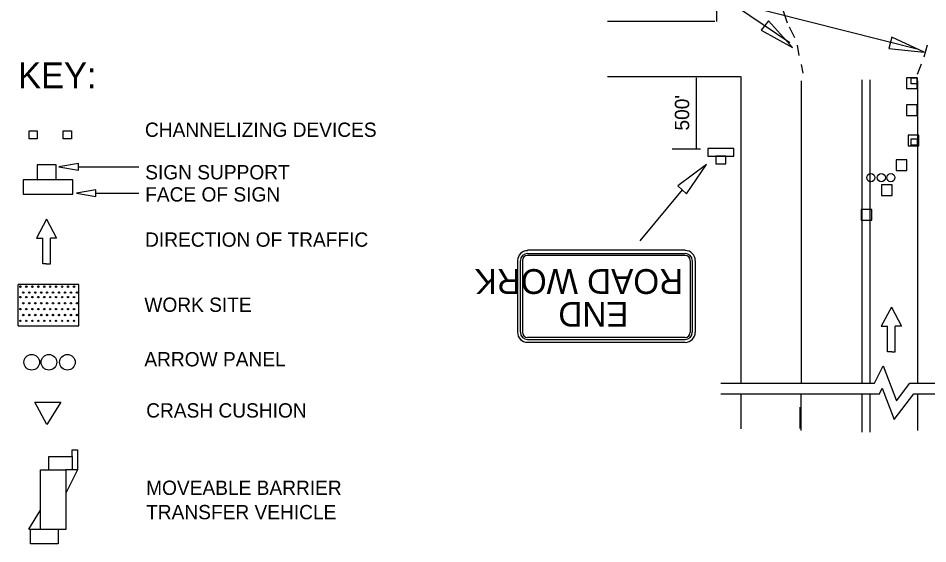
# Model space of a CAD drawing. Extents: x 1531.4 to 1538.6, y 1529.6 to 1539.6.
# Drawn here: x 1532.047 to 1535.863, y 1531.428 to 1533.633 of the extents above; entities that cross this region are included whole.
import ezdxf

# ---------------------------------------------------------------- set-up
doc = ezdxf.new("R2010")
doc.units = 0
for name, color, linetype in [('DETL-DIMS', 7, 'Continuous'), ('DETL-LINE', 7, 'Continuous'), ('DETL-NOTE', 7, 'Continuous'), ('DETL-TITL', 7, 'Continuous'), ('USER-BORD', 7, 'Continuous')]:
    doc.layers.add(name, color=color, linetype=linetype)

# ---------------------------------------------------------------- blocks, each defined once
blk = doc.blocks.new('CD1')
at = {"layer": 'USER-BORD'}
blk.add_lwpolyline([(0, 0.0312), (0.0312, 0.0312), (0.0312, 0), (0, 0)], close=True, dxfattribs=at)
blk = doc.blocks.new('DIR2')
at = {"layer": 'USER-BORD'}
for p, q in [((0, 0.0012), (-0.0342, -0.0477)), ((0, 0.0012), (0.0342, -0.0477)), ((-0.0342, -0.0477), (-0.0132, -0.0477)), ((-0.0132, -0.1133), (-0.0132, -0.0477)), ((0.0342, -0.0477), (0.0132, -0.0477)), ((0.0132, -0.1133), (0.0132, -0.0477)), ((-0.0011, -0.1133), (-0.0132, -0.1133)), ((-0.0011, -0.1133), (0.0011, -0.1133)), ((0.0011, -0.1133), (0.0132, -0.1133))]:
    blk.add_line(p, q, dxfattribs=at)
blk = doc.blocks.new('SIGN13')
at = {"layer": 'USER-BORD'}
for points in [[(-0.0134, 0.0182), (0.011, 0.0189), (0.011, 0.0371), (-0.0134, 0.0371)], [(-0.0314, 0.0182), (-0.0314, 0), (0.032, 0), (0.032, 0.0182)]]:
    blk.add_lwpolyline(points, close=True, dxfattribs=at)

msp = doc.modelspace()

# ---------------------------------------------------------------- linework, layer by layer
at = {"layer": 'DETL-DIMS'}
for p, q in [((1534.5458, 1534.0314), (1535.2841, 1533.5316)), ((1535.0528, 1533.6973), (1535.8242, 1533.5042)), ((1534.8912, 1533.3834), (1534.8912, 1533.082)), ((1534.9093, 1533.0841), (1534.7899, 1533.0841)), ((1532.2993, 1533.0101), (1532.5532, 1533.0101)), ((1532.3728, 1532.8989), (1532.5532, 1532.8989)), ((1534.8323, 1532.9132), (1534.6545, 1532.6987))]:
    msp.add_line(p, q, dxfattribs=at)
for points in [[(1535.1945, 1533.6221), (1535.1637, 1533.5837), (1535.2944, 1533.5105)], [(1535.7118, 1533.5541), (1535.6986, 1533.5066), (1535.8476, 1533.491)], [(1532.2993, 1532.9965), (1532.2993, 1533.0239), (1532.2173, 1533.0101)], [(1534.8146, 1532.9302), (1534.85, 1532.8961), (1534.9347, 1533.0197)], [(1532.3728, 1532.8853), (1532.3728, 1532.9127), (1532.2907, 1532.8989)]]:
    msp.add_lwpolyline(points, close=True, dxfattribs=at)
at = {"layer": 'DETL-LINE'}
for p, q in [((1534.9765, 1534.4718), (1534.9765, 1533.6202)), ((1535.1948, 1533.8478), (1535.2726, 1533.6143)), ((1534.9696, 1533.6189), (1534.5192, 1533.6189)), ((1535.2804, 1533.5971), (1535.303, 1533.5519)), ((1535.315, 1533.5203), (1535.3222, 1533.4769)), ((1535.8594, 1533.52), (1535.8462, 1533.4693)), ((1535.3312, 1533.4389), (1535.3384, 1533.4027)), ((1535.8352, 1533.4406), (1535.8176, 1533.3967)), ((1534.5192, 1533.3883), (1535.0767, 1533.3883)), ((1535.0782, 1533.3884), (1535.0782, 1533.1168)), ((1535.3309, 1533.3705), (1535.3309, 1532.1019)), ((1535.5858, 1533.3746), (1535.5858, 1533.103)), ((1535.62, 1533.3746), (1535.62, 1533.103)), ((1535.8196, 1533.3705), (1535.8196, 1532.1002)), ((1535.0782, 1533.1168), (1535.0782, 1532.1019)), ((1535.5858, 1533.103), (1535.5858, 1532.1019)), ((1535.62, 1533.103), (1535.62, 1532.1019)), ((1534.8448, 1532.6596), (1534.1838, 1532.6596)), ((1534.1838, 1532.6456), (1534.8448, 1532.6456)), ((1534.8448, 1532.6376), (1534.1838, 1532.6376)), ((1534.8446, 1532.6379), (1534.8443, 1532.6373)), ((1534.1418, 1532.6156), (1534.1418, 1532.3156)), ((1534.1538, 1532.3156), (1534.1538, 1532.6156)), ((1534.1628, 1532.6156), (1534.1628, 1532.3156)), ((1534.8668, 1532.3156), (1534.8668, 1532.6156)), ((1534.8748, 1532.6156), (1534.8748, 1532.3156)), ((1534.8878, 1532.3156), (1534.8878, 1532.6156)), ((1532.0467, 1532.342), (1532.0467, 1532.516)), ((1532.3007, 1532.516), (1532.0467, 1532.516)), ((1532.3007, 1532.516), (1532.0467, 1532.516)), ((1532.3007, 1532.516), (1532.0467, 1532.516)), ((1532.3007, 1532.516), (1532.0467, 1532.516)), ((1532.0468, 1532.342), (1532.0468, 1532.516)), ((1532.0553, 1532.5071), (1532.0553, 1532.5071)), ((1532.0561, 1532.5071), (1532.0561, 1532.5071)), ((1532.0809, 1532.5071), (1532.0809, 1532.5071)), ((1532.0809, 1532.5071), (1532.0809, 1532.5071)), ((1532.1057, 1532.5071), (1532.1057, 1532.5071)), ((1532.1065, 1532.5071), (1532.1065, 1532.5071)), ((1532.1305, 1532.5071), (1532.1305, 1532.5071)), ((1532.1313, 1532.5071), (1532.1313, 1532.5071)), ((1532.1553, 1532.5071), (1532.1553, 1532.5071)), ((1532.1561, 1532.5071), (1532.1561, 1532.5071)), ((1532.1809, 1532.5071), (1532.1809, 1532.5071)), ((1532.1809, 1532.5071), (1532.1809, 1532.5071)), ((1532.2057, 1532.5071), (1532.2057, 1532.5071)), ((1532.2057, 1532.5071), (1532.2057, 1532.5071)), ((1532.2305, 1532.5071), (1532.2305, 1532.5071)), ((1532.2313, 1532.5071), (1532.2313, 1532.5071)), ((1532.2553, 1532.5071), (1532.2553, 1532.5071)), ((1532.2561, 1532.5071), (1532.2561, 1532.5071)), ((1532.2809, 1532.5071), (1532.2809, 1532.5071)), ((1532.2809, 1532.5071), (1532.2809, 1532.5071)), ((1532.3007, 1532.342), (1532.3007, 1532.516)), ((1532.3007, 1532.342), (1532.3007, 1532.516)), ((1532.3007, 1532.342), (1532.3007, 1532.516)), ((1532.3007, 1532.342), (1532.3007, 1532.516)), ((1532.0681, 1532.4823), (1532.0681, 1532.4823)), ((1532.0681, 1532.4823), (1532.0681, 1532.4823)), ((1532.0929, 1532.4823), (1532.0929, 1532.4823)), ((1532.0929, 1532.4823), (1532.0929, 1532.4823)), ((1532.1185, 1532.4823), (1532.1185, 1532.4823)), ((1532.1185, 1532.4823), (1532.1185, 1532.4823)), ((1532.1433, 1532.4823), (1532.1433, 1532.4823)), ((1532.1433, 1532.4823), (1532.1433, 1532.4823)), ((1532.1681, 1532.4823), (1532.1681, 1532.4823)), ((1532.1681, 1532.4823), (1532.1681, 1532.4823)), ((1532.1929, 1532.4823), (1532.1929, 1532.4823)), ((1532.1929, 1532.4823), (1532.1929, 1532.4823)), ((1532.2177, 1532.4823), (1532.2177, 1532.4823)), ((1532.2177, 1532.4823), (1532.2177, 1532.4823)), ((1532.2433, 1532.4823), (1532.2433, 1532.4823)), ((1532.2433, 1532.4823), (1532.2433, 1532.4823)), ((1532.2681, 1532.4823), (1532.2681, 1532.4823)), ((1532.2681, 1532.4823), (1532.2681, 1532.4823)), ((1532.2929, 1532.4823), (1532.2929, 1532.4823)), ((1532.2929, 1532.4823), (1532.2929, 1532.4823)), ((1532.0553, 1532.4633), (1532.0553, 1532.4633)), ((1532.0561, 1532.4633), (1532.0561, 1532.4633)), ((1532.0681, 1532.4377), (1532.0681, 1532.4377)), ((1532.0809, 1532.4633), (1532.0809, 1532.4633)), ((1532.0809, 1532.4633), (1532.0809, 1532.4633)), ((1532.0929, 1532.4377), (1532.0929, 1532.4377)), ((1532.1057, 1532.4633), (1532.1057, 1532.4633)), ((1532.1065, 1532.4633), (1532.1065, 1532.4633)), ((1532.1185, 1532.4377), (1532.1185, 1532.4377)), ((1532.1305, 1532.4633), (1532.1305, 1532.4633)), ((1532.1313, 1532.4633), (1532.1313, 1532.4633)), ((1532.1433, 1532.4377), (1532.1433, 1532.4377)), ((1532.1553, 1532.4633), (1532.1553, 1532.4633)), ((1532.1561, 1532.4633), (1532.1561, 1532.4633)), ((1532.1681, 1532.4377), (1532.1681, 1532.4377)), ((1532.1809, 1532.4633), (1532.1809, 1532.4633)), ((1532.1809, 1532.4633), (1532.1809, 1532.4633)), ((1532.1929, 1532.4377), (1532.1929, 1532.4377)), ((1532.2057, 1532.4633), (1532.2057, 1532.4633)), ((1532.2057, 1532.4633), (1532.2057, 1532.4633)), ((1532.2177, 1532.4377), (1532.2177, 1532.4377)), ((1532.2305, 1532.4633), (1532.2305, 1532.4633)), ((1532.2313, 1532.4633), (1532.2313, 1532.4633)), ((1532.2433, 1532.4377), (1532.2433, 1532.4377)), ((1532.2553, 1532.4633), (1532.2553, 1532.4633)), ((1532.2561, 1532.4633), (1532.2561, 1532.4633)), ((1532.2681, 1532.4377), (1532.2681, 1532.4377)), ((1532.2809, 1532.4633), (1532.2809, 1532.4633)), ((1532.2809, 1532.4633), (1532.2809, 1532.4633)), ((1532.2929, 1532.4377), (1532.2929, 1532.4377)), ((1532.0553, 1532.4129), (1532.0553, 1532.4129)), ((1532.0561, 1532.4129), (1532.0561, 1532.4129)), ((1532.0809, 1532.4129), (1532.0809, 1532.4129)), ((1532.0809, 1532.4129), (1532.0809, 1532.4129)), ((1532.1057, 1532.4129), (1532.1057, 1532.4129)), ((1532.1065, 1532.4129), (1532.1065, 1532.4129)), ((1532.1305, 1532.4129), (1532.1305, 1532.4129)), ((1532.1313, 1532.4129), (1532.1313, 1532.4129)), ((1532.1553, 1532.4129), (1532.1553, 1532.4129)), ((1532.1561, 1532.4129), (1532.1561, 1532.4129)), ((1532.1809, 1532.4129), (1532.1809, 1532.4129)), ((1532.1809, 1532.4129), (1532.1809, 1532.4129)), ((1532.2057, 1532.4129), (1532.2057, 1532.4129)), ((1532.2057, 1532.4129), (1532.2057, 1532.4129)), ((1532.2305, 1532.4129), (1532.2305, 1532.4129)), ((1532.2313, 1532.4129), (1532.2313, 1532.4129)), ((1532.2553, 1532.4129), (1532.2553, 1532.4129)), ((1532.2561, 1532.4129), (1532.2561, 1532.4129)), ((1532.2809, 1532.4129), (1532.2809, 1532.4129)), ((1532.2809, 1532.4129), (1532.2809, 1532.4129)), ((1532.0553, 1532.3637), (1532.0553, 1532.3637)), ((1532.0561, 1532.3637), (1532.0561, 1532.3637)), ((1532.0681, 1532.3881), (1532.0681, 1532.3881)), ((1532.0681, 1532.3881), (1532.0681, 1532.3881)), ((1532.0809, 1532.3637), (1532.0809, 1532.3637)), ((1532.0809, 1532.3637), (1532.0809, 1532.3637)), ((1532.0929, 1532.3881), (1532.0929, 1532.3881)), ((1532.0929, 1532.3881), (1532.0929, 1532.3881)), ((1532.1057, 1532.3637), (1532.1057, 1532.3637)), ((1532.1065, 1532.3637), (1532.1065, 1532.3637)), ((1532.1185, 1532.3881), (1532.1185, 1532.3881)), ((1532.1185, 1532.3881), (1532.1185, 1532.3881)), ((1532.1305, 1532.3637), (1532.1305, 1532.3637)), ((1532.1313, 1532.3637), (1532.1313, 1532.3637)), ((1532.1433, 1532.3881), (1532.1433, 1532.3881)), ((1532.1433, 1532.3881), (1532.1433, 1532.3881)), ((1532.1553, 1532.3637), (1532.1553, 1532.3637)), ((1532.1561, 1532.3637), (1532.1561, 1532.3637)), ((1532.1681, 1532.3881), (1532.1681, 1532.3881)), ((1532.1681, 1532.3881), (1532.1681, 1532.3881)), ((1532.1809, 1532.3637), (1532.1809, 1532.3637)), ((1532.1809, 1532.3637), (1532.1809, 1532.3637)), ((1532.1929, 1532.3881), (1532.1929, 1532.3881)), ((1532.1929, 1532.3881), (1532.1929, 1532.3881)), ((1532.2057, 1532.3637), (1532.2057, 1532.3637)), ((1532.2057, 1532.3637), (1532.2057, 1532.3637)), ((1532.2177, 1532.3881), (1532.2177, 1532.3881)), ((1532.2177, 1532.3881), (1532.2177, 1532.3881)), ((1532.2305, 1532.3637), (1532.2305, 1532.3637)), ((1532.2313, 1532.3637), (1532.2313, 1532.3637)), ((1532.2433, 1532.3881), (1532.2433, 1532.3881)), ((1532.2433, 1532.3881), (1532.2433, 1532.3881)), ((1532.2553, 1532.3637), (1532.2553, 1532.3637)), ((1532.2561, 1532.3637), (1532.2561, 1532.3637)), ((1532.2681, 1532.3881), (1532.2681, 1532.3881)), ((1532.2681, 1532.3881), (1532.2681, 1532.3881)), ((1532.2809, 1532.3637), (1532.2809, 1532.3637)), ((1532.2809, 1532.3637), (1532.2809, 1532.3637)), ((1532.2929, 1532.3881), (1532.2929, 1532.3881)), ((1532.2929, 1532.3881), (1532.2929, 1532.3881)), ((1532.0467, 1532.342), (1532.3007, 1532.342)), ((1534.8448, 1532.2936), (1534.1838, 1532.2936)), ((1534.1838, 1532.2856), (1534.1838, 1532.2856)), ((1534.1838, 1532.2856), (1534.8448, 1532.2856)), ((1534.1838, 1532.2736), (1534.8448, 1532.2736)), ((1535.0782, 1532.057), (1535.0782, 1531.9108)), ((1535.3309, 1531.9038), (1535.3309, 1532.057)), ((1535.5858, 1532.057), (1535.5858, 1531.8969)), ((1535.62, 1532.057), (1535.62, 1531.8969)), ((1535.8196, 1532.057), (1535.8196, 1531.9038)), ((1532.117, 1532.0219), (1532.2257, 1532.0219)), ((1532.1666, 1531.9291), (1532.117, 1532.0219)), ((1532.2257, 1532.0219), (1532.1666, 1531.9291)), ((1532.2737, 1531.8228), (1532.2958, 1531.8228)), ((1532.2737, 1531.794), (1532.2737, 1531.8228)), ((1532.2958, 1531.8228), (1532.2958, 1531.739)), ((1532.1757, 1531.739), (1532.1757, 1531.7942)), ((1532.1757, 1531.7942), (1532.2737, 1531.7942)), ((1532.2737, 1531.7942), (1532.2737, 1531.739)), ((1532.1407, 1531.5785), (1532.1407, 1531.739)), ((1532.1407, 1531.739), (1532.2459, 1531.739)), ((1532.2808, 1531.739), (1532.2458, 1531.739)), ((1532.2459, 1531.739), (1532.2459, 1531.4883)), ((1532.295, 1531.7384), (1532.2459, 1531.641)), ((1532.2958, 1531.739), (1532.278, 1531.739)), ((1532.0916, 1531.4896), (1532.1407, 1531.5693)), ((1532.1407, 1531.4883), (1532.1407, 1531.5785)), ((1532.1407, 1531.5785), (1532.1407, 1531.5785)), ((1532.0916, 1531.4896), (1532.1407, 1531.4896)), ((1532.0981, 1531.4281), (1532.0981, 1531.4896)), ((1532.2459, 1531.4887), (1532.1407, 1531.4887)), ((1532.2142, 1531.4883), (1532.2142, 1531.4281)), ((1532.2142, 1531.4281), (1532.0981, 1531.4281))]:
    msp.add_line(p, q, dxfattribs=at)
for points in [[(1535.7736, 1533.3385), (1535.8184, 1533.3385), (1535.8184, 1533.3833), (1535.7736, 1533.3833)], [(1535.7736, 1533.2249), (1535.8184, 1533.2249), (1535.8184, 1533.2697), (1535.7736, 1533.2697)], [(1535.7805, 1533.0974), (1535.8253, 1533.0974), (1535.8253, 1533.1422), (1535.7805, 1533.1422)], [(1535.0491, 1533.055), (1535.0491, 1533.0863), (1534.9401, 1533.0863), (1534.9401, 1533.055)], [(1534.9736, 1533.0225), (1535.0156, 1533.0225), (1535.0156, 1533.055), (1534.9736, 1533.055)], [(1535.7306, 1532.9942), (1535.7754, 1532.9942), (1535.7754, 1533.039), (1535.7306, 1533.039)], [(1535.6686, 1532.8891), (1535.7134, 1532.8891), (1535.7134, 1532.9339), (1535.6686, 1532.9339)], [(1535.5825, 1532.7858), (1535.6273, 1532.7858), (1535.6273, 1532.8306), (1535.5825, 1532.8306)]]:
    msp.add_lwpolyline(points, close=True, dxfattribs=at)
for points in [[(1535.3309, 1533.2205), (1535.3309, 1533.1205)], [(1535.8196, 1533.2205), (1535.8196, 1533.1205)], [(1535.3309, 1532.8205), (1535.3309, 1532.7205)], [(1535.8196, 1532.8205), (1535.8196, 1532.7205)], [(1535.3309, 1532.4205), (1535.3309, 1532.3205)], [(1535.8196, 1532.4205), (1535.8196, 1532.3205)], [(1534.9943, 1532.1019), (1535.639, 1532.1019), (1535.6761, 1532.1751), (1535.7315, 1532.0286), (1535.7869, 1532.1019), (1536.09, 1532.1019)], [(1534.9943, 1532.057), (1535.6595, 1532.057), (1535.6717, 1532.0812), (1535.7217, 1531.949), (1535.8034, 1532.057), (1536.09, 1532.057)], [(1535.3257, 1532.0018), (1535.3257, 1531.9126)], [(1535.8196, 1531.9984), (1535.8196, 1531.9038)]]:
    msp.add_lwpolyline(points, dxfattribs=at)
for centre, radius in [((1535.6237, 1532.9645), 0.017), ((1535.6677, 1532.9645), 0.017), ((1535.7078, 1532.9645), 0.017), ((1532.056, 1532.507), 0.00291), ((1532.0808, 1532.507), 0.00291), ((1532.1064, 1532.507), 0.00291), ((1532.1312, 1532.507), 0.00291), ((1532.156, 1532.507), 0.00291), ((1532.1808, 1532.507), 0.00291), ((1532.2056, 1532.507), 0.00291), ((1532.2312, 1532.507), 0.00291), ((1532.256, 1532.507), 0.00291), ((1532.2808, 1532.507), 0.00291), ((1532.068, 1532.4822), 0.00291), ((1532.0928, 1532.4822), 0.00291), ((1532.1184, 1532.4822), 0.00291), ((1532.1432, 1532.4822), 0.00291), ((1532.168, 1532.4822), 0.00291), ((1532.1928, 1532.4822), 0.00291), ((1532.2176, 1532.4822), 0.00291), ((1532.2432, 1532.4822), 0.00291), ((1532.268, 1532.4822), 0.00291), ((1532.2928, 1532.4822), 0.00291), ((1532.056, 1532.4633), 0.00291), ((1532.068, 1532.4377), 0.00291), ((1532.0808, 1532.4633), 0.00291), ((1532.0928, 1532.4377), 0.00291), ((1532.1064, 1532.4633), 0.00291), ((1532.1184, 1532.4377), 0.00291), ((1532.1312, 1532.4633), 0.00291), ((1532.1432, 1532.4377), 0.00291), ((1532.156, 1532.4633), 0.00291), ((1532.168, 1532.4377), 0.00291), ((1532.1808, 1532.4633), 0.00291), ((1532.1928, 1532.4377), 0.00291), ((1532.2056, 1532.4633), 0.00291), ((1532.2176, 1532.4377), 0.00291), ((1532.2312, 1532.4633), 0.00291), ((1532.2432, 1532.4377), 0.00291), ((1532.256, 1532.4633), 0.00291), ((1532.268, 1532.4377), 0.00291), ((1532.2808, 1532.4633), 0.00291), ((1532.2928, 1532.4377), 0.00291), ((1532.056, 1532.4129), 0.00291), ((1532.0808, 1532.4129), 0.00291), ((1532.1064, 1532.4129), 0.00291), ((1532.1312, 1532.4129), 0.00291), ((1532.156, 1532.4129), 0.00291), ((1532.1808, 1532.4129), 0.00291), ((1532.2056, 1532.4129), 0.00291), ((1532.2312, 1532.4129), 0.00291), ((1532.256, 1532.4129), 0.00291), ((1532.2808, 1532.4129), 0.00291), ((1532.056, 1532.3637), 0.00291), ((1532.068, 1532.3881), 0.00291), ((1532.0808, 1532.3637), 0.00291), ((1532.0928, 1532.3881), 0.00291), ((1532.1064, 1532.3637), 0.00291), ((1532.1184, 1532.3881), 0.00291), ((1532.1312, 1532.3637), 0.00291), ((1532.1432, 1532.3881), 0.00291), ((1532.156, 1532.3637), 0.00291), ((1532.168, 1532.3881), 0.00291), ((1532.1808, 1532.3637), 0.00291), ((1532.1928, 1532.3881), 0.00291), ((1532.2056, 1532.3637), 0.00291), ((1532.2176, 1532.3881), 0.00291), ((1532.2312, 1532.3637), 0.00291), ((1532.2432, 1532.3881), 0.00291), ((1532.256, 1532.3637), 0.00291), ((1532.268, 1532.3881), 0.00291), ((1532.2808, 1532.3637), 0.00291), ((1532.2928, 1532.3881), 0.00291), ((1532.1033, 1532.1899), 0.0329), ((1532.1757, 1532.1899), 0.0329), ((1532.2532, 1532.1899), 0.0329)]:
    msp.add_circle(centre, radius, dxfattribs=at)
for centre, radius, start, end in [((1534.8446, 1532.6163), 0.0424, 0, 90), ((1534.1834, 1532.6163), 0.0415, 90, 180), ((1534.1834, 1532.6163), 0.0301, 90, 180), ((1534.1834, 1532.6163), 0.0216, 90, 180), ((1534.8446, 1532.6163), 0.0301, 0, 90), ((1534.8446, 1532.6163), 0.0216, 0, 90), ((1534.1834, 1532.3157), 0.0421, 180, 270), ((1534.1834, 1532.3157), 0.0301, 180, 270), ((1534.1834, 1532.3157), 0.0216, 180, 270), ((1534.8446, 1532.3157), 0.0424, 270, 0), ((1534.8446, 1532.3157), 0.0301, 270, 0), ((1534.8446, 1532.3157), 0.0216, 270, 0)]:
    msp.add_arc(centre, radius, start, end, dxfattribs=at)

# ---------------------------------------------------------------- block references
for name, p, xscale, yscale in [('CD1', (1535.7929, 1533.3574), 0.820627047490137, 0.820627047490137), ('CD1', (1532.0923, 1533.127), 1.0955237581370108, 1.0955237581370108), ('CD1', (1532.2355, 1533.127), 1.0955237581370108, 1.0955237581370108), ('CD1', (1535.7929, 1533.1013), 0.820627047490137, 0.820627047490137), ('SIGN13', (1532.1702, 1532.8958), 3.282508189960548, 3.282508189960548), ('DIR2', (1532.1658, 1532.7883), 1.2309405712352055, 1.641254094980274)]:
    msp.add_blockref(name, p, dxfattribs=dict(at, xscale=xscale, yscale=yscale))
at = {"layer": 'DETL-LINE', "xscale": 1.2309405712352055, "yscale": -1.641254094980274, "rotation": 180}
msp.add_blockref('DIR2', (1535.7098, 1532.4197), dxfattribs=at)

# ---------------------------------------------------------------- texts
at = {"layer": 'DETL-LINE'}
for s, p in [('ROAD WORK', (1534.8359, 1532.5806)), ('END', (1534.6069, 1532.4426))]:
    msp.add_text(s, height=0.1041, rotation=180, dxfattribs=at).set_placement(p)
at = {"layer": 'DETL-NOTE'}
msp.add_text("500'", height=0.06, rotation=90, dxfattribs=at).set_placement((1534.8616, 1533.162))
for s, p in [('CHANNELIZING DEVICES', (1532.5785, 1533.1355)), ('SIGN SUPPORT', (1532.5795, 1532.9571)), ('FACE OF SIGN', (1532.5795, 1532.8642)), ('DIRECTION OF TRAFFIC', (1532.5792, 1532.6746)), ('WORK SITE', (1532.576, 1532.4013)), ('ARROW PANEL', (1532.576, 1532.1725)), ('CRASH CUSHION', (1532.5837, 1531.9578)), ('MOVEABLE BARRIER', (1532.5834, 1531.6332)), ('TRANSFER VEHICLE', (1532.5834, 1531.5311))]:
    msp.add_text(s, height=0.06, dxfattribs=at).set_placement(p)
at = {"layer": 'DETL-TITL'}
msp.add_text('KEY:', height=0.108, dxfattribs=at).set_placement((1532.0462, 1533.3396))

doc.saveas('drawing.dxf')
